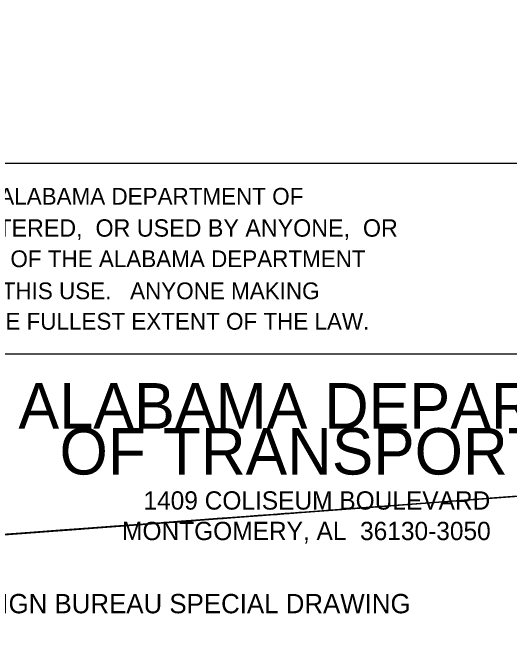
# Model space of a CAD drawing. Extents: x -1.2 to 9.9, y -0.1 to 1.8.
# Drawn here: x 2.5114 to 2.6951, y 0.1462 to 0.3811 of the extents above; entities that cross this region are included whole.
import ezdxf

# ---------------------------------------------------------------- set-up
doc = ezdxf.new("R2010")
doc.units = 0
doc.layers.add('Level 1', color=7, linetype='Continuous')

msp = doc.modelspace()

# ---------------------------------------------------------------- linework, layer by layer
at = {"layer": 'Level 1'}
msp.add_line((2.7668281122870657, 0.3252695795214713), (2.1884584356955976, 0.3252695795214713), dxfattribs=at)
msp.add_lwpolyline([(2.7668281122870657, 0.2547322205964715), (2.1884584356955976, 0.2547322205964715)], dxfattribs=at)
msp.add_spline([(2.4604328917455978, 0.18476013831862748), (2.4609905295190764, 0.18476013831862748), (2.4621210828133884, 0.18476013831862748), (2.4626939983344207, 0.18476013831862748), (2.4626939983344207, 0.18533305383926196), (2.463251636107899, 0.18476013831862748), (2.4649474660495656, 0.18476013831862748), (2.465505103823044, 0.18476013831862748), (2.466078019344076, 0.18476013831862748), (2.4666356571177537, 0.18476013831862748), (2.4666356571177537, 0.18476013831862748), (2.4677662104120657, 0.18476013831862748), (2.4688967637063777, 0.18476013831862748)], degree=3, dxfattribs=at)

# ---------------------------------------------------------------- texts
for s, height, p in [('THIS DRAWING REPRESENTS DESIGNS PREPARED FOR USE BY THE ALABAMA DEPARTMENT OF', 0.006205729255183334, (2.2251326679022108, 0.31003002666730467)), ('TRANSPORTATION AND IS NOT TO BE COPIED,  REPRODUCED,  ALTERED,  OR USED BY ANYONE,  OR', 0.006432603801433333, (2.2251326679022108, 0.29818213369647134)), ('ANY ORGANIZATION,  WITHOUT THE EXPRESSED WRITTEN CONSENT OF THE ALABAMA DEPARTMENT', 0.006205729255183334, (2.2251326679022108, 0.2868995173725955)), ('OF TRANSPORTATION REPRESENTATIVE AUTHORIZED TO APPROVE THIS USE.   ANYONE MAKING', 0.006205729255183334, (2.2251326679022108, 0.2750439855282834)), ('UNAUTHORIZED USE OF THIS DRAWING MAY BE PROSECUTED TO THE FULLEST EXTENT OF THE LAW.', 0.006205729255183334, (2.2251326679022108, 0.2637613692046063)), ('ALABAMA DEPARTMENT', 0.016927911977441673, (2.513477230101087, 0.22708713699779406)), ('OF TRANSPORTATION', 0.017168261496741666, (2.5287091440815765, 0.2101593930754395)), ('1409 COLISEUM BOULEVARD', 0.006771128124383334, (2.559745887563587, 0.19718094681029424)), ('MONTGOMERY, AL  36130-3050', 0.006771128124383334, (2.5518472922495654, 0.1858906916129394)), ('DESIGN BUREAU SPECIAL DRAWING', 0.007150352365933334, (2.4875203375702, 0.15881088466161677))]:
    msp.add_text(s, height=height, dxfattribs=at).set_placement(p)

doc.saveas('drawing.dxf')
